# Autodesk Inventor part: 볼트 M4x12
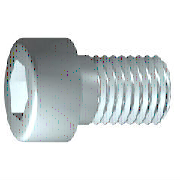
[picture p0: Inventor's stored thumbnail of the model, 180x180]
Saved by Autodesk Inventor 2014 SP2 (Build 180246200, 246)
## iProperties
IsCustomPart: 0
Created: 2012-02
Part Number: 볼트 M4x12
Material: 강철, 연강
Description: 6각 소켓 머리 캡 나사
Document SubType Name: Modeling
Standard: ISO 4762
Designer: mduedu
Standard Revision: Fourth edition 2004-03-01
Standards Organization: ISO
Language: ko-KR
Size Designation: M4 x 12
Categories: <MemberInstance><Categories><Category DisplayName="조임쇠" InternalName="e4da775c-781d-43d5-af7c-5136215cf5a6" Mnemonic="FSTN"><Category DisplayName="볼트" InternalN
Density: 7.75 g/cm^3
Appearance: 강철
Author: mduedu
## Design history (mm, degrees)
sketch "스케치1"
  geometry: L1 (-1, 0)-(12, 0); L2 (12, 0)-(12, 2); L3 (12, 2)-(1.75, 2); L4 (1.75, 2)-(1.32, 2); L5 (1.32, 2)-(0, 2); L6 (0, 2)-(0, 3.5); L7 (0, 3.5)-(-4, 3.5); L8 (-4, 3.5)-(-4, 1.732); L9 (-4, 1.732)-(-2, 1.732); L10 (-2, 1.732)-(-1, 0); L11 (-7.2, 0)-(15.2, 0) reference; L12 (0, -0.7)-(0, 4.2) reference; L13 (1.75, 2)-(0, 2)
  constraints: 22 end point, 6 parallel, 2 collinear, 2 perpendicular, 1 horizontal, 1 point on line
  dimensions: "d1" = 10.25 distance from line of L3.end L2 (= GEL); "d2" = 0.42952 distance of L4.end L3.end (computed from GAL); "d3" = 4 distance between parallel lines of L8 L6 (= KOH); "d4" = 2 distance of L8.end L9.end (= INTI); "d5" = 60 deg angle of L10 L1; "d6" = 4 diameter of L3 L1 (= GD); "d7" = 4 diameter of L5 L1 (= BDM); "d8" = 3.4641 diameter of L9 L1 (= 1.1547 x SW); "d9" = 7 diameter of L7 L1 (= KOD); "d26" = 12 distance between parallel lines of L12 L2 (= NLG)
revolve "본체" sketch "스케치1" stored, may be unused: angle "d10" = 90 deg
sketch "스케치2"
  geometry: L1 (0, -4.9)-(0, 4.9) reference; L2 (-4.9, 0)-(4.9, 0) reference; L3 (1.732, 0)-(0.866, -1.5); L4 (0.866, -1.5)-(-0.866, -1.5); L5 (-0.866, -1.5)-(-1.732, 0); L6 (-1.732, 0)-(-0.866, 1.5); L7 (-0.866, 1.5)-(0.866, 1.5); L8 (0.866, 1.5)-(1.732, 0); 2 further points
  constraints: 12 end point, 1 coincident, 1 horizontal alignment, 1 point on line, 12 other
extrude "슬롯" join sketch "스케치2" stored distance "d11" = 10; taper "d12" = 0 deg
workplane "Work Plane1"
fillet "Fillet2" dims "d30" = 0.1 (= R)
body "Solid1"
fillet "모깎기1" dims "d17" = 0.4 (= RR)
feature "스레드" dims "d13" = 10.25 (= GEL), "d14" = 0
chamfer "모따기1" distance "d15" = 0.42941 (= -0.5 x SPD + 0.5 x GD); stored, may be unused: second distance "d16" = 0.42941 (= GUL), angle "d27" = 45 deg
other parameters: "GD" = 4 [user parameter; used in 2 equation terms], "NLG" = 12 [user parameter; used in 1 equation term], "GEL" = 10.25 [user parameter; used in 2 equation terms], "KOD" = 7 [user parameter; used in 1 equation term], "KOH" = 4 [user parameter; used in 1 equation term], "INTI" = 2 [user parameter; used in 1 equation term], "GAL" = 0.42941 (= 0.61345 x PTC) [user parameter; used in 1 equation term], "GUL" = 0.42941 (= 0.61345 x PTC) [user parameter; used in 1 equation term], "BDM" = 4 (= NND) [user parameter; used in 1 equation term], "SW" = 3 [user parameter; used in 2 equation terms], "RR" = 0.4 [user parameter; used in 1 equation term], "SPD" = 3.14117 (= NND - 1.2269 x PTC) [user parameter; used in 1 equation term], "d19" = 0, "d28" = 0, "d29" = 0, "R" = 0.1 [user parameter; used in 1 equation term], "TOA" = 30 deg [user parameter], "GD1" = 3.14117 (= THREADDIA - 1.2269 x PTC) [user parameter], "THREADDIA" = 4 [user parameter; used in 1 equation term], "FAWI" = 45 deg [user parameter], "TPU" = 14.28571 (computed from PTC) [user parameter], "PTC" = 0.7 [user parameter; used in 5 equation terms], "NND" = 4 [user parameter; used in 2 equation terms], "E0" = 3.465 (= 1.155 x SW) [user parameter]
